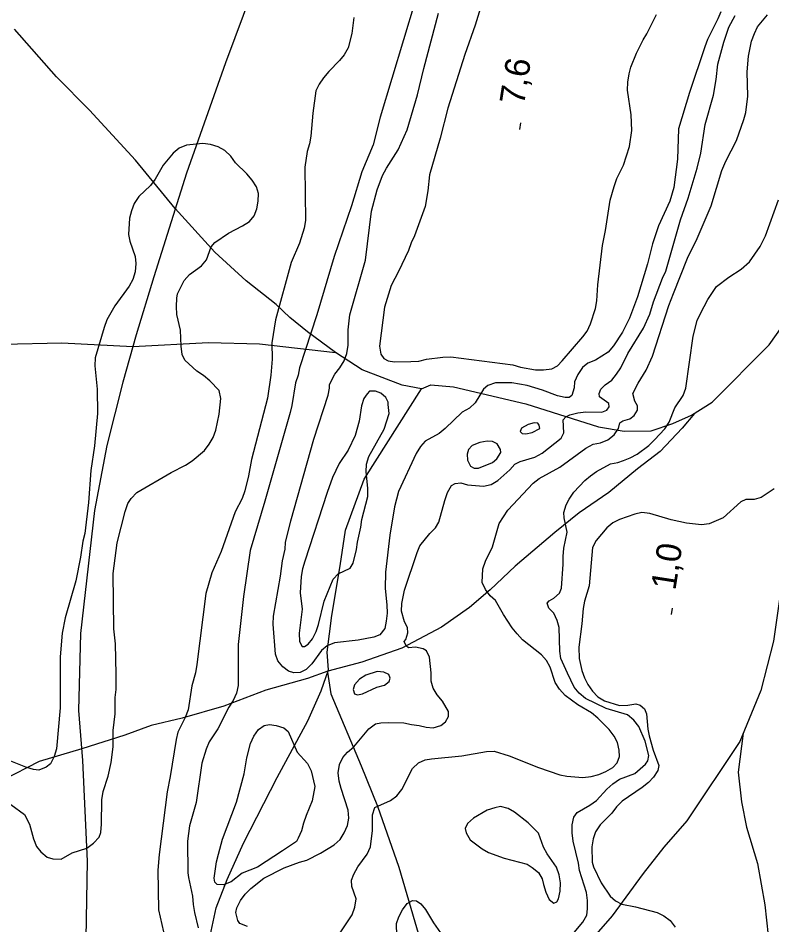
# Model space of a CAD drawing. Extents: x 282461 to 284471, y 5554090 to 5557646.
# Drawn here: x 282879.7 to 282970.5, y 5555176.2 to 5555285.4 of the extents above; entities that cross this region are included whole.
import ezdxf

# ---------------------------------------------------------------- set-up
doc = ezdxf.new("R2010")
doc.units = 0
for name, color, linetype in [('Niveau 1', 7, 'Continuous'), ('Niveau 2', 7, 'Continuous'), ('Niveau 22', 7, 'Continuous'), ('Niveau 3', 7, 'Continuous')]:
    doc.layers.add(name, color=color, linetype=linetype)

msp = doc.modelspace()

# ---------------------------------------------------------------- linework, layer by layer
at = {"layer": 'Niveau 1'}
for points in [[(282927.54, 5555287.44), (282923.32, 5555273.45), (282922.49, 5555270.14), (282921.14, 5555266.89), (282919.87, 5555262.77)], [(282926.76, 5555209.57), (282926.47, 5555209.8), (282926.23, 5555210.32), (282926.4, 5555210.55), (282926.68, 5555211.36), (282926.62, 5555212), (282926.26, 5555212.69), (282925.9, 5555213.96), (282925.95, 5555214.89), (282926.27, 5555216.51), (282927.78, 5555221.04), (282928.11, 5555221.85), (282929.31, 5555223.31), (282930, 5555224.01), (282930.39, 5555224.71), (282931.11, 5555227.32), (282931.45, 5555228.25), (282931.9, 5555229.12), (282932.36, 5555229.35), (282933.05, 5555229.42), (282933.86, 5555229.2), (282934.79, 5555229.09), (282935.77, 5555229.04), (282936.69, 5555229.23), (282937.5, 5555229.7), (282938.93, 5555230.98), (282939.55, 5555231.69), (282940.18, 5555231.98), (282941.97, 5555232.52), (282942.83, 5555232.99), (282945.12, 5555234.81), (282945.46, 5555235.45), (282945.38, 5555237.01), (282945.67, 5555237.36), (282946.18, 5555237.6), (282947.11, 5555237.84), (282948.09, 5555237.96), (282950, 5555237.93), (282950.63, 5555238.16), (282950.91, 5555238.57), (282950.85, 5555238.98), (282949.74, 5555239.77), (282949.68, 5555240.18), (282949.9, 5555240.7), (282950.42, 5555241.23), (282951.22, 5555241.81), (282951.79, 5555242.51), (282952.3, 5555243.27), (282953.15, 5555245.02), (282955.02, 5555248.04), (282955.8, 5555249.73), (282956.25, 5555251.24), (282957.31, 5555254.09), (282957.71, 5555254.9), (282959.48, 5555261.11), (282960.43, 5555263.72), (282961.49, 5555267.32), (282961.93, 5555269.12), (282962.46, 5555272.59), (282963.46, 5555276.13), (282963.78, 5555277.99), (282963.99, 5555279.84), (282964.71, 5555282.51), (282965.32, 5555284.31), (282966.06, 5555285.71)], [(282919.87, 5555262.77), (282917.8, 5555256.67), (282915.69, 5555249.65), (282913.63, 5555243.27), (282913.47, 5555242.4), (282913.14, 5555241.47), (282912.71, 5555238.75), (282912.49, 5555237.88), (282909.44, 5555227.21), (282907.66, 5555221.29), (282906.87, 5555215.73), (282906.24, 5555209.94), (282906.25, 5555205.02), (282906.03, 5555204.1), (282905.63, 5555203.22), (282905.12, 5555202.41), (282903.77, 5555199.79), (282902.75, 5555198.22), (282902.36, 5555197.35), (282901.86, 5555195.67), (282901.16, 5555190.92), (282900.39, 5555188.13), (282900.12, 5555186.28), (282900.17, 5555182.47), (282900.24, 5555181.89), (282900.73, 5555179.64), (282900.8, 5555178.66), (282900.98, 5555177.67), (282901.41, 5555175.83)], [(282907.36, 5555176), (282906.43, 5555176.34), (282906.19, 5555176.74), (282905.95, 5555177.67), (282906.06, 5555178.25), (282906.51, 5555179.12), (282907.08, 5555179.88), (282907.76, 5555180.58), (282909.31, 5555181.81), (282911.78, 5555183.05), (282913.62, 5555183.76), (282914.48, 5555184), (282916.15, 5555184.83), (282917.81, 5555185.83), (282918.5, 5555186.47), (282919.01, 5555187.28), (282919.4, 5555188.16), (282919.56, 5555189.03), (282919.49, 5555190.01), (282918.65, 5555192.6), (282918.41, 5555193.52), (282918.28, 5555194.51), (282918.44, 5555195.49), (282918.84, 5555196.36), (282919.41, 5555197), (282920.15, 5555197.65), (282921.97, 5555199.81), (282922.77, 5555200.39), (282923.41, 5555200.52), (282924.33, 5555200.58), (282926.18, 5555200.54), (282927.11, 5555200.32), (282928.03, 5555200.22), (282928.85, 5555199.99), (282929.71, 5555199.94), (282930.64, 5555200.19), (282931.21, 5555200.65), (282931.55, 5555201.29), (282931.54, 5555201.87), (282930.83, 5555203.14), (282930.19, 5555203.88), (282929.71, 5555204.69), (282929.47, 5555205.55), (282929.46, 5555206.54), (282929.26, 5555208.44), (282928.91, 5555209.19), (282928.5, 5555209.42), (282927.57, 5555209.64), (282926.76, 5555209.57)]]:
    msp.add_lwpolyline(points, dxfattribs=at)
at = {"layer": 'Niveau 2'}
for points in [[(282937.48, 5555293.46), (282934.76, 5555284.53), (282933.53, 5555281), (282931.48, 5555274.56), (282930.54, 5555270.92), (282929.27, 5555266.51), (282929.06, 5555264.61), (282928.74, 5555262.7), (282927.46, 5555259.16), (282927.06, 5555258.35), (282926.73, 5555257.42), (282925.55, 5555254.87), (282924.64, 5555253.18), (282923.87, 5555250.57), (282923.23, 5555245.89), (282923.42, 5555244.91), (282923.77, 5555244.39), (282924.29, 5555244.11), (282925.05, 5555244), (282927.01, 5555244.02), (282927.99, 5555244.09), (282928.91, 5555244.33), (282930.87, 5555244.58), (282931.85, 5555244.59), (282939.3, 5555243.63), (282940.23, 5555243.35), (282942.02, 5555243.03), (282943, 5555243.04), (282943.98, 5555243.16), (282944.67, 5555243.52), (282945.24, 5555244.1), (282947.75, 5555247.01), (282948.26, 5555247.71), (282948.65, 5555248.58), (282949.26, 5555250.44), (282949.42, 5555251.36), (282949.52, 5555253.27), (282950.09, 5555258.01), (282950.47, 5555259.81), (282951.01, 5555263.45), (282951.5, 5555265.13), (282951.84, 5555266.06), (282952.63, 5555267.69), (282953.35, 5555269.95), (282953.62, 5555271.86), (282953.53, 5555273.76), (282953.09, 5555276.7), (282953.14, 5555277.68), (282953.3, 5555278.67), (282953.52, 5555279.48), (282954.19, 5555281.16), (282954.98, 5555282.79), (282955.43, 5555283.48), (282956.62, 5555285.81)], [(282923.27, 5555211.14), (282922.58, 5555210.85), (282920.68, 5555210.48), (282917.85, 5555210.16), (282916.93, 5555209.8), (282916.25, 5555209.22), (282915.11, 5555207.65), (282914.43, 5555206.95), (282913.68, 5555206.59), (282912.93, 5555206.53), (282912.29, 5555206.75), (282911.59, 5555207.26), (282911.01, 5555208.01), (282910.71, 5555208.81), (282910.43, 5555212.39), (282910.48, 5555213.38), (282911.34, 5555218.18), (282911.55, 5555220.03), (282911.88, 5555221.42), (282911.93, 5555222.23), (282912.59, 5555224.84), (282915.35, 5555234.69), (282917.08, 5555239.97), (282917.24, 5555240.84), (282917.24, 5555241.25), (282917.86, 5555242.52), (282918.48, 5555243.28), (282918.99, 5555244.1), (282919.33, 5555245.02), (282919.49, 5555246.01), (282919.46, 5555247.86), (282919.67, 5555249.65), (282921.56, 5555256.26), (282922.29, 5555262.16), (282922.95, 5555264.71), (282923.62, 5555266.45), (282924.08, 5555267.33), (282925.49, 5555269.54), (282926.56, 5555271.92), (282927.84, 5555276.15), (282928.6, 5555279.34), (282930.37, 5555286)], [(282964.33, 5555286.14), (282964, 5555285.32), (282962.76, 5555282.83), (282962.42, 5555281.95), (282960.58, 5555276.44), (282959.25, 5555272.04), (282959.12, 5555268.39), (282958.7, 5555264.98), (282958.2, 5555263.35), (282956.85, 5555260.39), (282956.13, 5555258.19), (282955.52, 5555255.81), (282954.3, 5555251.81), (282953.35, 5555249.25), (282952.5, 5555247.57), (282951.43, 5555245.94), (282950.8, 5555245.18), (282949.25, 5555244.18), (282948.33, 5555243.83), (282947.7, 5555243.3), (282947.14, 5555242.48), (282946.74, 5555241.61), (282946.69, 5555240.86), (282946.42, 5555239.93), (282946.07, 5555239.7), (282945.61, 5555239.69), (282944.68, 5555239.92), (282942.89, 5555240.59), (282941.03, 5555241.15), (282939.18, 5555241.48), (282937.22, 5555241.46), (282936.29, 5555241.16), (282935.78, 5555240.69), (282934.76, 5555239.06), (282934.08, 5555238.42), (282933.22, 5555237.95), (282931.16, 5555235.96), (282930.42, 5555235.37), (282928.75, 5555234.43), (282928.19, 5555233.79), (282927.68, 5555232.97), (282925.54, 5555228.39), (282925.04, 5555226.53), (282924.51, 5555223.12), (282923.98, 5555218.66), (282923.95, 5555216.7), (282924.15, 5555214.73), (282924.16, 5555213.75), (282924.06, 5555212.77), (282923.89, 5555211.9), (282923.27, 5555211.14)], [(282920.17, 5555285.46), (282919.91, 5555283.55), (282919.46, 5555281.81), (282919.01, 5555280.99), (282918.44, 5555280.29), (282917.13, 5555278.95), (282916.5, 5555278.19), (282915.99, 5555277.43), (282915.6, 5555276.62)], [(282952.16, 5555196.48), (282952.09, 5555197.23), (282951.9, 5555198.15), (282951.49, 5555198.9), (282950.9, 5555199.71), (282949.55, 5555201.08), (282948.79, 5555201.71), (282947.11, 5555202.68), (282945.59, 5555203.82), (282944.94, 5555204.57), (282944.41, 5555205.37), (282943.81, 5555207.22), (282943.34, 5555208.02), (282942.75, 5555208.71), (282940.47, 5555210.54), (282939.83, 5555211.23), (282939.24, 5555211.97), (282938.18, 5555213.58), (282937.23, 5555215.25), (282936.59, 5555215.82), (282936, 5555216.57), (282935.59, 5555217.43), (282935.68, 5555219.06), (282936.02, 5555219.99), (282936.86, 5555221.73), (282937.64, 5555224.52), (282938.72, 5555226.15), (282941.74, 5555229.37), (282942.49, 5555229.95), (282944.96, 5555231.31), (282948.11, 5555233.6), (282948.97, 5555234.07), (282949.84, 5555234.26), (282950.76, 5555234.61), (282951.51, 5555235.2), (282952.02, 5555235.96), (282952.18, 5555236.65), (282952.53, 5555236.89), (282953.39, 5555237.13), (282953.91, 5555237.54), (282954.3, 5555238.18), (282954.3, 5555238.7), (282954, 5555239.28), (282953.76, 5555240.2), (282954.38, 5555241.42), (282955.34, 5555243), (282956.13, 5555244.68), (282958.08, 5555250.78), (282958.64, 5555252.24), (282960.33, 5555256.48), (282961.51, 5555258.87), (282963.2, 5555262.77), (282964.48, 5555267.06), (282964.93, 5555268.17), (282966.23, 5555270.67), (282967.12, 5555273.17), (282967.34, 5555274.04), (282967.61, 5555276.01), (282967.52, 5555278.91), (282967.67, 5555280.82), (282968.05, 5555282.62), (282968.39, 5555283.55), (282968.78, 5555284.36), (282969.98, 5555285.77)], [(282915.6, 5555276.62), (282915.22, 5555273.95), (282914.97, 5555271.17), (282914.81, 5555270.24), (282914.53, 5555269.31), (282914.26, 5555267.46), (282914.34, 5555261.03), (282914.18, 5555260.1), (282913.62, 5555258.3), (282912.61, 5555255.98), (282910.73, 5555249.07), (282910.3, 5555246.29), (282910.33, 5555244.32), (282910.18, 5555242.41), (282909.75, 5555239.62), (282907.82, 5555232.25), (282907.49, 5555230.28), (282907.05, 5555228.48), (282906.72, 5555227.55), (282905.87, 5555225.92), (282904.19, 5555221.16), (282903.07, 5555218.6), (282902.35, 5555216.11), (282901.24, 5555207.53), (282901.08, 5555206.54), (282900.64, 5555204.98), (282900.21, 5555202.08), (282899.87, 5555201.15), (282898.97, 5555199.4), (282898.75, 5555198.53), (282898.05, 5555194.07), (282897.67, 5555192.21), (282896.72, 5555184.68), (282896.57, 5555182.77), (282896.63, 5555178.02), (282897.24, 5555175.37)], [(282880.51, 5555189.49), (282881.1, 5555188.34), (282881.59, 5555186.55), (282881.95, 5555185.62), (282882.47, 5555184.99), (282883.23, 5555184.36), (282883.93, 5555184.14), (282884.92, 5555184.09), (282886.24, 5555184.86), (282888.02, 5555185.45), (282888.83, 5555186.04), (282889.51, 5555186.74), (282889.68, 5555187.32), (282889.78, 5555188.31), (282889.8, 5555191.26), (282889.96, 5555192.25), (282890.58, 5555194.11), (282890.96, 5555195.74), (282891.17, 5555197.65), (282891.2, 5555199.62), (282891.41, 5555201.59), (282891.44, 5555203.56), (282891.55, 5555204.54), (282891.53, 5555206.4), (282891.48, 5555210.05), (282891.28, 5555211.84), (282891.2, 5555218.5), (282891.68, 5555222.21), (282892.61, 5555225.99), (282892.95, 5555226.92), (282893.35, 5555227.56), (282894.03, 5555228.26), (282898.17, 5555230.68), (282899.89, 5555231.56), (282900.7, 5555232.09), (282902.19, 5555233.33), (282902.76, 5555234.09), (282903.21, 5555234.9), (282903.55, 5555235.77), (282903.93, 5555237.69), (282904.13, 5555239.6), (282903.95, 5555240.53), (282902.83, 5555241.73), (282902.07, 5555242.36), (282901.26, 5555242.87), (282899.8, 5555244.19), (282899.5, 5555244.88), (282899.37, 5555245.87), (282899.29, 5555247.83), (282898.86, 5555249.68), (282898.79, 5555250.67), (282898.83, 5555251.65), (282898.94, 5555252.18), (282899.73, 5555253.81), (282900.36, 5555254.51), (282901.8, 5555255.57), (282902.42, 5555256.27), (282902.98, 5555257.84), (282903.44, 5555258.36), (282905.05, 5555259.48), (282906.77, 5555260.37), (282907.58, 5555260.9), (282908.15, 5555261.6), (282908.48, 5555262.41), (282908.64, 5555263.34), (282908.69, 5555264.27), (282908.45, 5555265.08), (282907.92, 5555265.88), (282907.27, 5555266.63), (282905.93, 5555267.95), (282905.34, 5555268.75), (282904.63, 5555269.44), (282903.82, 5555269.9), (282902.89, 5555270.18), (282901.96, 5555270.28), (282900, 5555270.09), (282899.13, 5555269.73), (282898.39, 5555269.14), (282897.19, 5555267.68), (282896.23, 5555265.99), (282895.66, 5555265.23), (282894.29, 5555263.89), (282893.72, 5555263.07), (282893.38, 5555262.2), (282893.16, 5555261.32), (282893.01, 5555259.35), (282893.19, 5555258.54), (282893.85, 5555256.7), (282893.92, 5555255.83), (282893.82, 5555254.84), (282893.54, 5555253.91), (282893.09, 5555253.1), (282891.38, 5555250.76), (282890.42, 5555249.07), (282890.08, 5555248.14), (282889.03, 5555244.48), (282888.98, 5555243.5), (282889.25, 5555240.72), (282889.28, 5555237.77), (282888.93, 5555233.88), (282888.5, 5555230.92)], [(282945.47, 5555225.21), (282945.46, 5555225.84), (282945.74, 5555226.77), (282946.08, 5555227.47), (282946.64, 5555228.29), (282947.96, 5555229.69), (282948.65, 5555230.28), (282949.39, 5555230.81), (282951.06, 5555231.7), (282951.93, 5555231.88), (282952.62, 5555232.12), (282953.43, 5555232.42), (282954.29, 5555232.89), (282955.67, 5555233.94), (282956.35, 5555234.59), (282957.61, 5555235.94), (282958.12, 5555236.75), (282958.79, 5555238.44), (282959.82, 5555239.96), (282960.15, 5555240.83), (282961, 5555247.1), (282961.5, 5555248.96), (282961.9, 5555249.83), (282962.8, 5555251.52), (282963.83, 5555253.09), (282965.32, 5555254.21), (282966.81, 5555255.15), (282967.79, 5555256.03), (282969.09, 5555257.9), (282969.72, 5555259.18), (282971.28, 5555263.49)], [(282924.3, 5555238.86), (282924.3, 5555239.14), (282924, 5555239.72), (282923.42, 5555240.23), (282922.78, 5555240.46), (282922.03, 5555240.45), (282921.75, 5555240.16), (282921.35, 5555239.58), (282921.07, 5555238.71), (282920.81, 5555236.86), (282920.31, 5555235.12), (282919.46, 5555233.38), (282918.39, 5555231.75), (282917.6, 5555230.07), (282916.93, 5555228.27), (282914.26, 5555219.98), (282913.99, 5555219.06), (282913.83, 5555218.13), (282913.68, 5555216.17), (282913.93, 5555214.21), (282913.56, 5555211.31), (282913.63, 5555210.33), (282913.93, 5555209.7), (282914.22, 5555209.7), (282914.68, 5555210), (282915.19, 5555210.64), (282915.64, 5555211.51), (282915.92, 5555212.38), (282916.57, 5555215.16), (282917.69, 5555217.82), (282918.26, 5555218.47), (282919.7, 5555219.17), (282920.09, 5555219.76), (282920.48, 5555221.38), (282920.58, 5555222.3), (282921.02, 5555224.1), (282921.13, 5555225.02), (282921.84, 5555227.8), (282921.83, 5555228.78), (282921.63, 5555230.74), (282921.68, 5555231.67), (282921.96, 5555232.59), (282923.82, 5555235.91), (282924.43, 5555237.76), (282924.3, 5555238.86)], [(282942.48, 5555236.37), (282942.3, 5555236.6), (282941.89, 5555236.65), (282941.15, 5555236.47), (282940.34, 5555236), (282940.18, 5555235.59), (282940.41, 5555235.36), (282940.87, 5555235.31), (282941.62, 5555235.49), (282942.54, 5555235.96), (282942.48, 5555236.37)], [(282937.42, 5555234.12), (282936.84, 5555234.4), (282936.2, 5555234.45), (282935.34, 5555234.27), (282934.42, 5555233.91), (282933.96, 5555233.45), (282933.8, 5555232.87), (282933.86, 5555232.17), (282934.22, 5555231.42), (282934.63, 5555231.2), (282935.15, 5555231.2), (282936.87, 5555231.86), (282937.39, 5555232.33), (282937.84, 5555233.08), (282937.83, 5555233.43), (282937.42, 5555234.12)], [(282888.5, 5555230.92), (282888.2, 5555227.04), (282887.79, 5555223.33), (282887.51, 5555222.4), (282887.24, 5555220.49), (282886.7, 5555217.64), (282885.42, 5555213.17), (282885.04, 5555211.31), (282884.79, 5555208.47), (282884.81, 5555202.33), (282884.35, 5555197.4), (282884.07, 5555196.48), (282883.62, 5555195.6), (282883.1, 5555195.19), (282882.24, 5555194.83), (282881.6, 5555194.89), (282880.67, 5555195.17), (282878.87, 5555195.9)], [(282970.77, 5555228.69), (282969.22, 5555227.68), (282968.36, 5555227.44), (282967.37, 5555227.43), (282966.74, 5555227.14), (282964.62, 5555225.2), (282962.95, 5555224.49), (282962.02, 5555224.36), (282960.22, 5555224.58), (282958.36, 5555224.96), (282955.8, 5555225.75), (282954.82, 5555225.85), (282954.01, 5555225.67), (282952.16, 5555225.01), (282951.35, 5555224.6), (282950.61, 5555224.01), (282949.35, 5555222.49), (282948.9, 5555221.62), (282948.49, 5555217.03), (282947.94, 5555215.17), (282947.77, 5555214.3), (282947.62, 5555212.44), (282947.25, 5555209.65), (282947.27, 5555208.26), (282947.63, 5555206.82), (282947.93, 5555205.95), (282948.35, 5555205.14), (282948.88, 5555204.34), (282949.53, 5555203.65), (282950.34, 5555203.19), (282952.15, 5555202.63), (282953.13, 5555202.64), (282954.11, 5555202.83), (282954.64, 5555202.66), (282955.16, 5555202.2), (282955.4, 5555201.62), (282955.54, 5555199.77), (282955.73, 5555198.96), (282956.21, 5555197.22), (282956.87, 5555195.38)], [(282946.49, 5555175.05), (282947.75, 5555176.51), (282948.2, 5555177.38), (282948.3, 5555178.14), (282948.29, 5555179.12), (282948.16, 5555180.1), (282947.32, 5555182.76), (282947.19, 5555183.63), (282946.58, 5555186.29), (282946.46, 5555187.27), (282946.44, 5555188.26), (282946.66, 5555189.18), (282947.06, 5555189.71), (282948.56, 5555190.59), (282949.36, 5555191.18), (282950.62, 5555192.53), (282951.36, 5555193.17), (282952.16, 5555193.76), (282954.01, 5555194.42), (282955.27, 5555195.53), (282955.55, 5555195.94), (282955.66, 5555196.58), (282955.24, 5555198.31), (282954.46, 5555200.1), (282953.87, 5555200.84), (282953.11, 5555201.47), (282950.55, 5555202.26), (282948.05, 5555203.45), (282947.29, 5555204.08), (282946.7, 5555204.83), (282945.87, 5555206.5), (282945.1, 5555208.29), (282944.97, 5555209.15), (282944.88, 5555211.99), (282944.64, 5555212.86), (282944.22, 5555213.72), (282943.63, 5555214.35), (282943.45, 5555214.93), (282943.68, 5555215.22), (282944.25, 5555215.52), (282944.94, 5555216.16), (282945.17, 5555216.74), (282945.36, 5555219.64), (282945.35, 5555220.57), (282945.45, 5555221.56), (282945.84, 5555223.47), (282945.47, 5555225.21)], [(282922.98, 5555206.69), (282921.6, 5555206.27), (282920.85, 5555205.8), (282920.22, 5555205.1), (282920.06, 5555204.52), (282920.24, 5555204), (282920.59, 5555203.89), (282921.22, 5555204.01), (282922.94, 5555204.84), (282923.86, 5555205.08), (282924.43, 5555205.49), (282924.54, 5555205.9), (282924.37, 5555206.36), (282923.79, 5555206.64), (282922.98, 5555206.69)], [(282911.58, 5555185.13), (282908.54, 5555183.14), (282906.71, 5555182.42), (282905.39, 5555181.37), (282904.47, 5555181.01), (282903.72, 5555181.07), (282903.43, 5555181.35), (282903.36, 5555181.81), (282903.63, 5555183.78), (282903.85, 5555184.71), (282904.35, 5555186.5), (282906.02, 5555190.97), (282906.96, 5555194.39), (282907.28, 5555196.3), (282907.72, 5555198.04), (282908.12, 5555198.91), (282908.69, 5555199.72), (282909.37, 5555200.19), (282910.01, 5555200.31), (282910.82, 5555200.21), (282911.74, 5555199.93), (282912.27, 5555199.47), (282913.34, 5555197), (282914.57, 5555195.62), (282915.04, 5555194.76), (282915.47, 5555192.86), (282915.14, 5555191.12), (282914.41, 5555189.38), (282914.08, 5555188.45), (282913.86, 5555187.52), (282913.47, 5555186.65), (282913.24, 5555186.25), (282911.58, 5555185.13)], [(282918.35, 5555175.01), (282919.94, 5555177.39), (282920.28, 5555178.32), (282920.44, 5555179.31), (282919.9, 5555180.81), (282919.89, 5555181.56), (282920.17, 5555182.32), (282920.62, 5555183.19), (282921.76, 5555184.71), (282922.16, 5555185.58), (282922.42, 5555187.55), (282922.4, 5555189.46), (282922.68, 5555190.33), (282924.57, 5555191.16), (282925.32, 5555191.74), (282925.95, 5555192.5), (282927.24, 5555195.01), (282927.93, 5555195.71), (282928.74, 5555196.06), (282929.49, 5555196.19), (282933.18, 5555196.57), (282936.13, 5555197.07), (282937.05, 5555197.13), (282938.85, 5555196.57), (282942.4, 5555195.16), (282944.95, 5555194.26), (282945.82, 5555194.1), (282947.73, 5555193.94), (282948.72, 5555194.07), (282949.64, 5555194.31), (282950.5, 5555194.67), (282951.36, 5555195.14), (282951.88, 5555195.72), (282952.16, 5555196.48)], [(282956.87, 5555195.38), (282956.76, 5555194.79), (282956.25, 5555193.98), (282955.62, 5555193.33), (282954.88, 5555192.75), (282952.46, 5555191.1), (282951.78, 5555190.4), (282951.21, 5555189.64), (282949.83, 5555188.23), (282949.26, 5555187.41), (282948.98, 5555186.54), (282948.82, 5555185.61), (282948.84, 5555183.76), (282949.03, 5555183.18), (282949.92, 5555181.27), (282951.04, 5555179.66), (282951.68, 5555179.09), (282952.44, 5555178.69), (282954.07, 5555178.36), (282956.68, 5555177.69), (282957.5, 5555177.29), (282958.26, 5555176.72), (282958.85, 5555175.92)], [(282877.18, 5555191.89), (282880.51, 5555189.49)], [(282941.15, 5555188.49), (282939.51, 5555189.75), (282938.76, 5555190.2), (282937.83, 5555190.43), (282937.14, 5555190.3), (282936.21, 5555190), (282934.55, 5555189.06), (282933.86, 5555188.42), (282933.58, 5555187.78), (282933.7, 5555187.26), (282934.17, 5555186.45), (282935.63, 5555185.37), (282936.39, 5555184.91), (282938.25, 5555184.24), (282941.04, 5555183.51), (282941.62, 5555183.11), (282942.38, 5555182.49), (282942.85, 5555181.74), (282942.98, 5555181.04), (282943.28, 5555180.12), (282943.69, 5555179.26), (282944.22, 5555178.8), (282944.62, 5555178.98), (282944.79, 5555179.33), (282945.01, 5555180.26), (282945.06, 5555181.24), (282944.87, 5555182.22), (282944.57, 5555183.14), (282943.45, 5555184.75), (282942.98, 5555185.56), (282942.38, 5555187.23), (282941.15, 5555188.49)], [(282925.38, 5555173.38), (282925.29, 5555176.34), (282925.57, 5555177.15), (282926.02, 5555178.02), (282926.59, 5555178.78), (282927.22, 5555179.14), (282927.69, 5555179.08), (282928.21, 5555178.74), (282928.8, 5555178.05), (282929.74, 5555176.44), (282931.45, 5555174.03)]]:
    msp.add_lwpolyline(points, dxfattribs=at)
at = {"layer": 'Niveau 22'}
for points in [[(282945.47, 5555425.59), (282943.64, 5555419.4), (282942.24, 5555413.83), (282941.01, 5555407.54), (282938.73, 5555398.1), (282938.04, 5555392.99), (282937.04, 5555386.74), (282935.71, 5555379.67), (282932.48, 5555364.28), (282930, 5555354.22), (282927.51, 5555345.15), (282924.95, 5555336.32), (282922.5, 5555328.87), (282914.44, 5555306.18), (282904.7, 5555280), (282900.03, 5555266.72), (282896.07, 5555254.22)], [(282928.29, 5555240.76), (282925.98, 5555241.2), (282921.16, 5555243.05), (282917.94, 5555245.14), (282914.57, 5555247.62), (282912.46, 5555249.32), (282910.82, 5555250.91), (282907.19, 5555253.76), (282903.44, 5555257.19), (282898.65, 5555262.46), (282893.88, 5555268.28), (282888.32, 5555274.3), (282884.35, 5555278.32), (282879.31, 5555284.05)], [(282896.07, 5555254.22), (282893.96, 5555247.25), (282892.35, 5555241.55), (282890.42, 5555233.94), (282888.95, 5555226.11), (282887.25, 5555211.28), (282887.02, 5555202.01), (282887.5, 5555196), (282888.06, 5555183.86), (282887.91, 5555174.6)], [(282974.53, 5555252.32), (282973.32, 5555240.57), (282972.1, 5555226.78), (282971.85, 5555220.35), (282971.44, 5555215.7), (282970.7, 5555210.36), (282969.15, 5555204.43), (282966.62, 5555198.29), (282960.25, 5555188.71), (282957.5, 5555185.55), (282954.99, 5555182.39), (282951.26, 5555177.3), (282949.32, 5555175.08)], [(282902.49, 5555173.2), (282903.6, 5555178.23), (282904.89, 5555181.67), (282906.86, 5555186.05), (282910.92, 5555193.94), (282914.64, 5555200.77), (282916.21, 5555204.37), (282917.1, 5555206.92), (282916.96, 5555209.03), (282917.49, 5555213.45), (282918.52, 5555219.43), (282919.16, 5555223.71), (282921.39, 5555229.85), (282928.29, 5555240.76), (282929.44, 5555241.24), (282932.16, 5555240.97), (282940.85, 5555238.96), (282949.63, 5555236.17), (282952.72, 5555235.65), (282955.97, 5555235.67), (282958.57, 5555236.56), (282960.83, 5555237.56), (282963.31, 5555239.14), (282970.17, 5555246.05), (282973.77, 5555251.13)], [(282817.97, 5555199.1), (282823.38, 5555201.69), (282830.07, 5555206.08), (282832.29, 5555207.87), (282834.53, 5555210.16), (282838.43, 5555215.34), (282840.82, 5555218.83), (282843.22, 5555223.88), (282845.26, 5555227.49), (282848.02, 5555231.62), (282851.38, 5555234.94), (282853.79, 5555236.71), (282860.41, 5555242.07), (282861.68, 5555242.78), (282865.21, 5555244.54), (282867.63, 5555245.26), (282870.75, 5555245.98), (282885.02, 5555246.3), (282893.56, 5555245.83), (282902.68, 5555246.32), (282908.82, 5555246.17), (282917.94, 5555245.14)], [(282961.16, 5555237.77), (282959.68, 5555236.03), (282957.05, 5555233.22), (282954.3, 5555231.1), (282950.85, 5555228.28), (282947.29, 5555225.81), (282944.36, 5555223.44), (282939.6, 5555219.41), (282936.57, 5555216.55), (282934.1, 5555214.43), (282930.72, 5555212.03), (282925.95, 5555209.51), (282921.12, 5555207.84), (282917.04, 5555206.76), (282914.57, 5555205.85), (282909.56, 5555204.45), (282904.49, 5555202.52), (282899.47, 5555201.09), (282895.76, 5555200.2), (282892.59, 5555199.05), (282887.39, 5555197.38), (282882.27, 5555195.87), (282877.91, 5555193.63)], [(282917, 5555206.63), (282917.37, 5555204.03), (282921.05, 5555195.33), (282923.01, 5555190.49), (282925.59, 5555183.14), (282929.64, 5555169.28)], [(282967.03, 5555199.27), (282966.44, 5555194.59), (282966.84, 5555191), (282967.45, 5555187.98), (282968.78, 5555183.59), (282969.66, 5555178.61), (282970.05, 5555174.9)]]:
    msp.add_lwpolyline(points, dxfattribs=at)
at = {"layer": 'Niveau 3'}
for p, q in [((282940.16, 5555271.99), (282940.28, 5555272.78)), ((282958.39, 5555213.56), (282958.51, 5555214.35))]:
    msp.add_line(p, q, dxfattribs=at)

# ---------------------------------------------------------------- texts
for s, p in [('7,6  ', (282940.64, 5555274.83)), ('1,0  ', (282958.87, 5555216.4))]:
    msp.add_text(s, height=3, rotation=81.0957, dxfattribs=at).set_placement(p)

doc.saveas('drawing.dxf')
